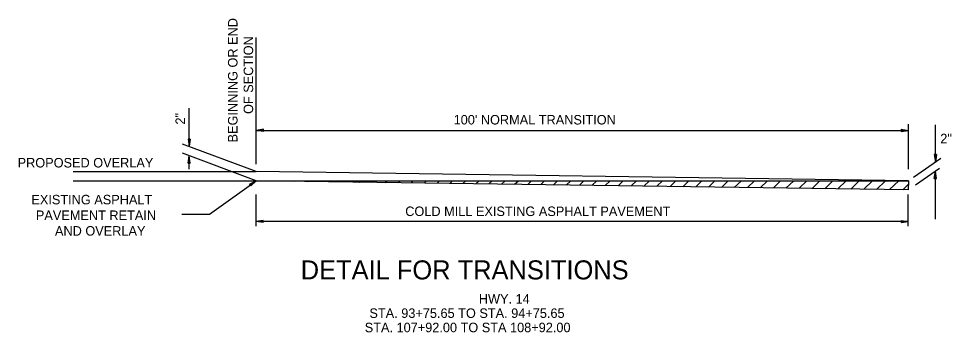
# Model space of a CAD drawing. Extents: x 635488 to 635865, y 290537 to 290973.
# Drawn here: x 635630.6 to 635689.4, y 290937 to 290956.8 of the extents above; entities that cross this region are included whole.
import ezdxf

# ---------------------------------------------------------------- set-up
doc = ezdxf.new("R2010")
doc.units = 0
doc.layers.add('Default', color=7, linetype='Continuous')

msp = doc.modelspace()

# ---------------------------------------------------------------- linework, layer by layer
at = {"layer": 'Default'}
for p, q in [((635645.579, 290947.658), (635645.579, 290955.645)), ((635641.36, 290948.792), (635641.36, 290951.192)), ((635646.046, 290949.858), (635645.579, 290949.792)), ((635646.046, 290949.837), (635645.647, 290949.792)), ((635646.046, 290949.837), (635645.735, 290949.792)), ((635646.046, 290949.725), (635646.046, 290949.858)), ((635686.268, 290949.858), (635686.735, 290949.792)), ((635686.268, 290949.858), (635686.268, 290949.725)), ((635686.268, 290949.837), (635686.58, 290949.792)), ((635686.268, 290949.837), (635686.644, 290949.792)), ((635686.735, 290947.349), (635686.735, 290950.191)), ((635688.422, 290947.792), (635688.422, 290950.146)), ((635641.293, 290949.237), (635641.36, 290948.792)), ((635641.293, 290949.237), (635641.36, 290948.859)), ((635641.426, 290949.237), (635641.293, 290949.237)), ((635641.316, 290949.237), (635641.36, 290948.948)), ((635641.316, 290949.237), (635641.36, 290949.014)), ((635641.338, 290949.237), (635641.36, 290949.103)), ((635641.338, 290949.237), (635641.36, 290949.169)), ((635641.426, 290949.237), (635641.36, 290948.792)), ((635641.381, 290949.237), (635641.36, 290949.103)), ((635641.405, 290949.237), (635641.36, 290948.948)), ((635641.405, 290949.237), (635641.36, 290948.859)), ((635641.381, 290949.237), (635641.36, 290949.014)), ((635641.36, 290949.237), (635641.36, 290949.169)), ((635645.579, 290949.792), (635686.735, 290949.792)), ((635646.046, 290949.725), (635645.579, 290949.792)), ((635646.046, 290949.725), (635645.647, 290949.792)), ((635646.046, 290949.747), (635645.735, 290949.792)), ((635646.046, 290949.814), (635645.825, 290949.792)), ((635646.046, 290949.747), (635645.825, 290949.792)), ((635646.046, 290949.814), (635645.891, 290949.792)), ((635646.046, 290949.77), (635645.891, 290949.792)), ((635646.046, 290949.792), (635645.979, 290949.792)), ((635646.046, 290949.77), (635645.979, 290949.792)), ((635686.268, 290949.814), (635686.423, 290949.792)), ((635686.268, 290949.814), (635686.491, 290949.792)), ((635686.268, 290949.725), (635686.735, 290949.792)), ((635686.268, 290949.77), (635686.423, 290949.792)), ((635686.268, 290949.747), (635686.58, 290949.792)), ((635686.268, 290949.725), (635686.644, 290949.792)), ((635686.268, 290949.747), (635686.491, 290949.792)), ((635686.268, 290949.77), (635686.335, 290949.792)), ((635686.268, 290949.792), (635686.335, 290949.792)), ((635645.579, 290947.193), (635640.938, 290948.926)), ((635645.579, 290946.616), (635640.938, 290948.348)), ((635641.293, 290947.726), (635641.36, 290948.192)), ((635641.293, 290947.726), (635641.36, 290948.126)), ((635641.426, 290947.726), (635641.36, 290948.192)), ((635641.36, 290947.349), (635641.36, 290948.192)), ((635641.405, 290947.726), (635641.36, 290948.126)), ((635688.356, 290948.259), (635688.422, 290947.792)), ((635688.489, 290948.259), (635688.356, 290948.259)), ((635688.378, 290948.259), (635688.422, 290947.948)), ((635688.378, 290948.259), (635688.422, 290947.882)), ((635688.399, 290948.259), (635688.422, 290948.104)), ((635688.399, 290948.259), (635688.422, 290948.037)), ((635688.489, 290948.259), (635688.422, 290947.792)), ((635688.444, 290948.259), (635688.422, 290948.104)), ((635688.467, 290948.259), (635688.422, 290947.948)), ((635688.489, 290948.259), (635688.422, 290947.882)), ((635688.467, 290948.259), (635688.422, 290948.037)), ((635688.422, 290948.259), (635688.422, 290948.192)), ((635688.444, 290948.259), (635688.422, 290948.192)), ((635641.293, 290947.726), (635641.426, 290947.726)), ((635641.316, 290947.726), (635641.36, 290948.037)), ((635641.316, 290947.726), (635641.36, 290947.971)), ((635641.338, 290947.726), (635641.36, 290947.882)), ((635641.338, 290947.726), (635641.36, 290947.792)), ((635641.405, 290947.726), (635641.36, 290948.037)), ((635641.381, 290947.726), (635641.36, 290947.971)), ((635641.381, 290947.726), (635641.36, 290947.882)), ((635641.36, 290947.726), (635641.36, 290947.792)), ((635687.045, 290946.839), (635688.777, 290948.037)), ((635634.031, 290947.192), (635645.579, 290947.192)), ((635686.735, 290946.616), (635645.579, 290947.193)), ((635687.178, 290946.349), (635688.689, 290947.415)), ((635688.356, 290946.749), (635688.422, 290947.216)), ((635688.378, 290946.749), (635688.422, 290947.149)), ((635688.378, 290946.749), (635688.422, 290947.059)), ((635688.399, 290946.749), (635688.422, 290946.993)), ((635688.399, 290946.749), (635688.422, 290946.903)), ((635688.422, 290944.195), (635688.422, 290947.216)), ((635688.489, 290946.749), (635688.422, 290947.216)), ((635688.489, 290946.749), (635688.422, 290947.149)), ((635688.467, 290946.749), (635688.422, 290947.059)), ((635688.467, 290946.749), (635688.422, 290946.993)), ((635688.444, 290946.749), (635688.422, 290946.903)), ((635634.031, 290946.615), (635686.735, 290946.615)), ((635642.649, 290944.506), (635645.579, 290946.616)), ((635645.158, 290946.393), (635645.579, 290946.616)), ((635645.158, 290946.393), (635645.246, 290946.283)), ((635645.18, 290946.393), (635645.513, 290946.571)), ((635645.18, 290946.393), (635645.447, 290946.527)), ((635645.18, 290946.371), (635645.379, 290946.482)), ((635645.18, 290946.371), (635645.335, 290946.439)), ((635645.203, 290946.349), (635645.268, 290946.393)), ((635645.203, 290946.349), (635645.268, 290946.393)), ((635645.224, 290946.304), (635645.447, 290946.527)), ((635645.224, 290946.327), (635645.379, 290946.482)), ((635645.224, 290946.327), (635645.335, 290946.439)), ((635645.246, 290946.283), (635645.579, 290946.616)), ((635645.246, 290946.304), (635645.513, 290946.571)), ((635686.712, 290946.037), (635645.579, 290946.616)), ((635647.2, 290946.593), (635647.223, 290946.616)), ((635648.011, 290946.582), (635648.044, 290946.616)), ((635648.821, 290946.57), (635648.888, 290946.616)), ((635649.652, 290946.559), (635649.711, 290946.616)), ((635650.465, 290946.547), (635650.532, 290946.616)), ((635651.275, 290946.536), (635651.354, 290946.616)), ((635652.086, 290946.525), (635652.176, 290946.616)), ((635652.916, 290946.513), (635653.02, 290946.616)), ((635653.726, 290946.502), (635653.842, 290946.616)), ((635654.559, 290946.489), (635654.664, 290946.616)), ((635655.349, 290946.479), (635655.486, 290946.616)), ((635656.181, 290946.467), (635656.329, 290946.616)), ((635656.991, 290946.456), (635657.152, 290946.616)), ((635657.822, 290946.444), (635657.974, 290946.616)), ((635658.61, 290946.433), (635658.817, 290946.616)), ((635659.445, 290946.422), (635659.639, 290946.616)), ((635660.255, 290946.41), (635660.461, 290946.616)), ((635661.066, 290946.397), (635661.284, 290946.615)), ((635661.875, 290946.387), (635662.126, 290946.616)), ((635662.708, 290946.375), (635662.947, 290946.616)), ((635663.518, 290946.363), (635663.769, 290946.616)), ((635664.328, 290946.353), (635664.591, 290946.616)), ((635665.138, 290946.341), (635665.434, 290946.616)), ((635665.971, 290946.329), (635666.256, 290946.616)), ((635666.758, 290946.318), (635667.078, 290946.616)), ((635667.592, 290946.306), (635667.901, 290946.616)), ((635668.423, 290946.295), (635668.722, 290946.616)), ((635669.234, 290946.283), (635669.566, 290946.616)), ((635670.045, 290946.272), (635670.387, 290946.616)), ((635670.855, 290946.261), (635671.21, 290946.616)), ((635671.689, 290946.249), (635672.054, 290946.616)), ((635672.499, 290946.238), (635672.876, 290946.616)), ((635673.309, 290946.226), (635673.697, 290946.616)), ((635674.118, 290946.215), (635674.518, 290946.616)), ((635674.951, 290946.203), (635675.362, 290946.616)), ((635675.74, 290946.192), (635676.185, 290946.616)), ((635676.572, 290946.181), (635677.006, 290946.616)), ((635677.383, 290946.169), (635677.828, 290946.616)), ((635678.214, 290946.157), (635678.651, 290946.616)), ((635679.001, 290946.146), (635679.494, 290946.616)), ((635679.834, 290946.134), (635680.316, 290946.616)), ((635680.649, 290946.127), (635681.138, 290946.616)), ((635681.456, 290946.112), (635681.959, 290946.616)), ((635682.266, 290946.1), (635682.803, 290946.616)), ((635683.098, 290946.088), (635683.625, 290946.616)), ((635683.908, 290946.077), (635684.448, 290946.616)), ((635684.719, 290946.065), (635685.268, 290946.616)), ((635685.529, 290946.054), (635686.113, 290946.616)), ((635686.361, 290946.042), (635686.726, 290946.407)), ((635686.735, 290946.616), (635686.712, 290946.037)), ((635688.356, 290946.749), (635688.489, 290946.749)), ((635688.444, 290946.749), (635688.422, 290946.839)), ((635688.422, 290946.749), (635688.422, 290946.839)), ((635645.579, 290943.75), (635645.579, 290945.749)), ((635686.712, 290943.75), (635686.712, 290945.749)), ((635640.894, 290944.506), (635642.649, 290944.506)), ((635646.025, 290944.105), (635645.579, 290944.04)), ((635646.025, 290944.105), (635645.579, 290944.04)), ((635686.712, 290944.04), (635645.579, 290944.04)), ((635646.025, 290943.972), (635645.579, 290944.04)), ((635646.025, 290943.972), (635645.579, 290944.04)), ((635646.025, 290944.105), (635645.647, 290944.04)), ((635646.025, 290944.105), (635645.647, 290944.04)), ((635646.025, 290943.995), (635645.647, 290944.04)), ((635646.025, 290943.995), (635645.647, 290944.04)), ((635646.025, 290944.085), (635645.735, 290944.04)), ((635646.025, 290944.085), (635645.735, 290944.04)), ((635646.025, 290943.995), (635645.735, 290944.04)), ((635646.025, 290943.995), (635645.735, 290944.04)), ((635646.025, 290944.085), (635645.802, 290944.04)), ((635646.025, 290944.085), (635645.802, 290944.04)), ((635646.025, 290944.017), (635645.802, 290944.04)), ((635646.025, 290944.017), (635645.802, 290944.04)), ((635646.025, 290944.06), (635645.891, 290944.04)), ((635646.025, 290944.06), (635645.891, 290944.04)), ((635646.025, 290944.017), (635645.891, 290944.04)), ((635646.025, 290944.017), (635645.891, 290944.04)), ((635646.025, 290944.06), (635645.958, 290944.04)), ((635646.025, 290944.06), (635645.958, 290944.04)), ((635646.025, 290944.04), (635645.958, 290944.04)), ((635646.025, 290944.04), (635645.958, 290944.04)), ((635646.025, 290943.972), (635646.025, 290944.105)), ((635646.025, 290943.972), (635646.025, 290944.105)), ((635686.268, 290944.105), (635686.712, 290944.04)), ((635686.268, 290944.105), (635686.644, 290944.04)), ((635686.268, 290944.105), (635686.268, 290943.972)), ((635686.268, 290944.085), (635686.556, 290944.04)), ((635686.268, 290944.085), (635686.491, 290944.04)), ((635686.268, 290944.06), (635686.402, 290944.04)), ((635686.268, 290944.06), (635686.335, 290944.04)), ((635686.268, 290943.972), (635686.712, 290944.04)), ((635686.268, 290944.017), (635686.402, 290944.04)), ((635686.268, 290943.995), (635686.556, 290944.04)), ((635686.268, 290943.995), (635686.644, 290944.04)), ((635686.268, 290944.017), (635686.491, 290944.04)), ((635686.268, 290944.04), (635686.335, 290944.04))]:
    msp.add_line(p, q, dxfattribs=at)

# ---------------------------------------------------------------- texts
for s, p in [('BEGINNING OR END', (635644.406, 290949.031)), ('OF SECTION', (635645.392, 290950.826)), ('2"', (635641.094, 290950.159))]:
    msp.add_text(s, height=0.6, rotation=90, dxfattribs=at).set_placement(p)
for s, height, p in [("100' NORMAL TRANSITION", 0.6, (635658.039, 290950.161)), ('2"', 0.6, (635688.734, 290948.975)), ('PROPOSED OVERLAY', 0.6, (635630.536, 290947.449)), ('EXISTING ASPHALT', 0.6, (635631.404, 290945.122)), ('PAVEMENT RETAIN', 0.6, (635631.688, 290944.136)), ('COLD MILL EXISTING ASPHALT PAVEMENT', 0.6, (635654.986, 290944.386)), ('AND OVERLAY', 0.6, (635632.892, 290943.15)), ('DETAIL FOR TRANSITIONS', 1.2, (635648.393, 290940.388)), ('HWY. 14', 0.6, (635659.627, 290938.859)), ('STA. 93+75.65 TO STA. 94+75.65', 0.6, (635652.727, 290937.958)), ('STA. 107+92.00 TO STA 108+92.00', 0.6, (635652.431, 290937.056))]:
    msp.add_text(s, height=height, dxfattribs=at).set_placement(p)

doc.saveas('drawing.dxf')
